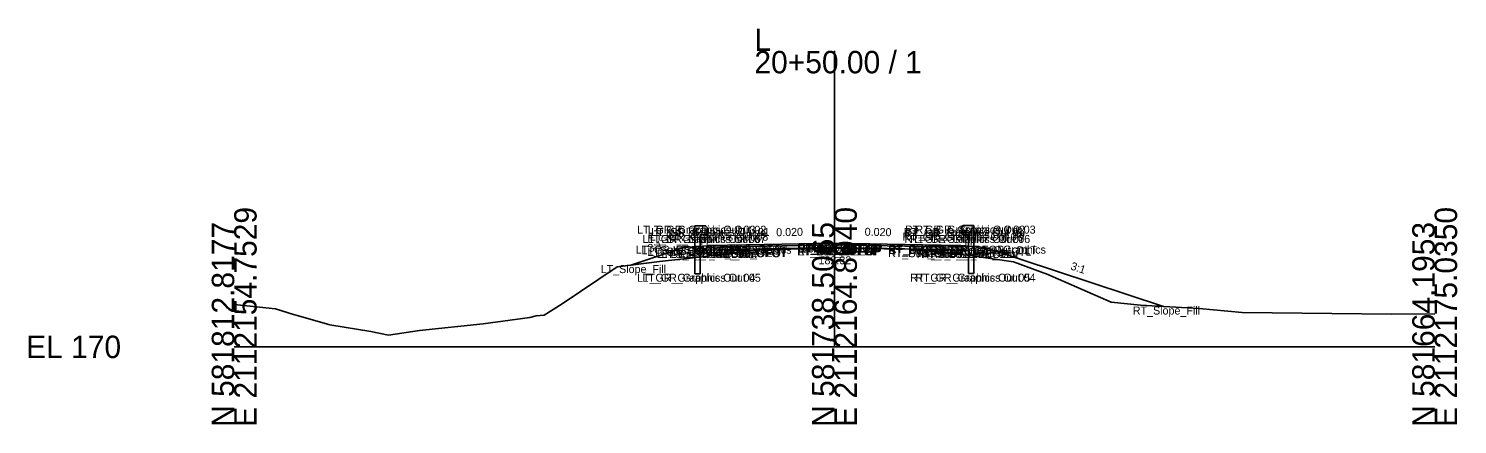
# Model space of a CAD drawing. Extents: x -486 to 1153, y -333 to 9539.
# Drawn here: x 974.3 to 1152.8, y 1490.3 to 1539.8 of the extents above; entities that cross this region are included whole.
import ezdxf

# ---------------------------------------------------------------- set-up
doc = ezdxf.new("R2010")
doc.units = 0
for name, color, linetype in [('Default', 7, 'Continuous'), ('Exist Cross Section Cell', 7, 'Continuous'), ('Exist XS Ground Line', 7, 'Continuous'), ('Prop CMT Guardrail Graphics', 7, 'Continuous'), ('Prop CMT Pvmt Course 1', 7, 'Continuous'), ('Prop CMT Pvmt Course 2', 7, 'Continuous'), ('Prop CMT Pvmt Course 3', 7, 'Continuous'), ('Prop CMT Pvmt Surface', 7, 'Continuous'), ('Prop CMT Pvmt Surface Shoulder', 7, 'Continuous'), ('Prop CMT Shld Paved Course 1', 7, 'Continuous'), ('Prop CMT Shld Paved Course 2', 7, 'Continuous'), ('Prop CMT Shld Paved Course 3', 7, 'Continuous'), ('Prop CMT Slope Grass', 7, 'Continuous'), ('Prop CMT Subgrade Earthwork', 7, 'Continuous'), ('Prop XS Earthwork Shape', 7, 'Continuous'), ('Prop XS SE Text', 7, 'Continuous'), ('Prop XS Side Slope Text', 7, 'Continuous'), ('Scratch_Level_0', 7, 'Continuous')]:
    doc.layers.add(name, color=color, linetype=linetype)

msp = doc.modelspace()

# ---------------------------------------------------------------- linework, layer by layer
at = {"layer": 'Exist Cross Section Cell'}
for p, q in [((1075, 1500), (1075, 1536.98)), ((1000, 1500), (1075, 1500)), ((1075, 1500), (1150, 1500))]:
    msp.add_line(p, q, dxfattribs=at)
at = {"layer": 'Exist XS Ground Line'}
for p, q in [((1067.82, 1512.15), (1074.8, 1512.33)), ((1074.8, 1512.33), (1077.65, 1512.28)), ((1077.65, 1512.28), (1084.77, 1512.2)), ((1084.77, 1512.2), (1088.79, 1511.79)), ((1047.84, 1510), (1053.16, 1510.68)), ((1053.16, 1510.68), (1058.11, 1511.21)), ((1058.11, 1511.21), (1065.16, 1512.09)), ((1065.16, 1512.09), (1067.82, 1512.15)), ((1088.79, 1511.79), (1092.19, 1511.37)), ((1092.19, 1511.37), (1097.38, 1510.62)), ((1097.38, 1510.62), (1101.65, 1509.04)), ((1040.99, 1505.38), (1047.84, 1510)), ((1101.65, 1509.04), (1109.57, 1505.6)), ((1000, 1505.3), (1005.15, 1504.74)), ((1038.72, 1503.97), (1040.99, 1505.38)), ((1109.57, 1505.6), (1113.26, 1505.2)), ((1113.26, 1505.2), (1120.59, 1504.79)), ((1005.15, 1504.74), (1007.42, 1504.05)), ((1007.42, 1504.05), (1008.03, 1503.89)), ((1008.03, 1503.89), (1011.95, 1502.75)), ((1031.11, 1502.88), (1036.95, 1503.68)), ((1036.95, 1503.68), (1037.74, 1503.86)), ((1037.74, 1503.86), (1038.72, 1503.97)), ((1120.59, 1504.79), (1125.96, 1504.3)), ((1125.96, 1504.3), (1144.66, 1504.1)), ((1144.66, 1504.1), (1150, 1504.13)), ((1011.95, 1502.75), (1017.07, 1501.94)), ((1017.07, 1501.94), (1019.29, 1501.47)), ((1019.29, 1501.47), (1023.14, 1502.04)), ((1023.14, 1502.04), (1031.11, 1502.88))]:
    msp.add_line(p, q, dxfattribs=at)
at = {"layer": 'Prop CMT Guardrail Graphics'}
for points in [[(1057.56, 1509.14), (1057.56, 1515.14)], [(1057.56, 1515.14), (1058.89, 1515.14), (1059.16, 1514.85)], [(1059.16, 1514.27), (1058.89, 1513.98), (1058.22, 1513.98)], [(1058.22, 1513.98), (1058.22, 1509.14)], [(1059.16, 1514.85), (1058.89, 1514.56)], [(1058.89, 1514.56), (1059.16, 1514.27)], [(1092.4, 1515.15), (1091.06, 1515.15), (1090.79, 1514.85)], [(1090.79, 1514.85), (1091.06, 1514.56)], [(1091.06, 1514.56), (1090.79, 1514.27)], [(1090.79, 1514.27), (1091.06, 1513.98), (1091.73, 1513.98)], [(1091.73, 1513.98), (1091.73, 1509.15)], [(1092.4, 1509.15), (1092.4, 1515.15)], [(1058.22, 1509.14), (1057.56, 1509.14)], [(1091.73, 1509.15), (1092.4, 1509.15)]]:
    msp.add_lwpolyline(points, dxfattribs=at)
at = {"layer": 'Prop CMT Pvmt Course 1'}
for points in [[(1075, 1512.97), (1064, 1512.75)], [(1064, 1512.54), (1075, 1512.76)], [(1064, 1512.75), (1064, 1512.54)], [(1075, 1512.76), (1075, 1512.97)], [(1075, 1512.97), (1086, 1512.75)], [(1075, 1512.76), (1075, 1512.97)], [(1086, 1512.54), (1075, 1512.76)], [(1086, 1512.75), (1086, 1512.54)]]:
    msp.add_lwpolyline(points, dxfattribs=at)
msp.add_lwpolyline([(1075, 1512.76), (1075, 1512.84), (1075, 1512.84), (1075, 1512.76)], close=True, dxfattribs=at)
msp.add_lwpolyline([(1075, 1512.76), (1075, 1512.84), (1075, 1512.84), (1075, 1512.76)], close=True, dxfattribs=at)
at = {"layer": 'Prop CMT Pvmt Course 2'}
for points in [[(1075, 1512.76), (1064, 1512.54)], [(1064, 1512.54), (1064, 1512.21)], [(1064, 1512.21), (1075, 1512.43)], [(1075, 1512.43), (1075, 1512.76)], [(1075, 1512.43), (1075, 1512.76)], [(1075, 1512.76), (1086, 1512.54)], [(1086, 1512.21), (1075, 1512.43)], [(1086, 1512.54), (1086, 1512.21)]]:
    msp.add_lwpolyline(points, dxfattribs=at)
at = {"layer": 'Prop CMT Pvmt Course 3'}
for points in [[(1075, 1512.43), (1064, 1512.21)], [(1064, 1512.21), (1064, 1512.21)], [(1075, 1512.43), (1075, 1512.43)], [(1075, 1512.43), (1086, 1512.21)], [(1075, 1512.43), (1075, 1512.43)], [(1086, 1512.21), (1086, 1512.21)]]:
    msp.add_lwpolyline(points, dxfattribs=at)
at = {"layer": 'Prop CMT Pvmt Surface'}
for points in [[(1075, 1512.97), (1064, 1512.75)], [(1075, 1512.97), (1086, 1512.75)]]:
    msp.add_lwpolyline(points, dxfattribs=at)
at = {"layer": 'Prop CMT Pvmt Surface Shoulder'}
for points in [[(1064, 1512.75), (1059.26, 1512.65)], [(1086, 1512.75), (1090.69, 1512.65)]]:
    msp.add_lwpolyline(points, dxfattribs=at)
at = {"layer": 'Prop CMT Shld Paved Course 1'}
for points in [[(1064, 1512.75), (1059.26, 1512.65), (1059.05, 1512.44)], [(1059.05, 1512.44), (1064, 1512.54)], [(1064, 1512.54), (1064, 1512.75)], [(1086, 1512.75), (1090.69, 1512.65), (1090.9, 1512.44)], [(1086, 1512.54), (1086, 1512.75)], [(1090.9, 1512.44), (1086, 1512.54)]]:
    msp.add_lwpolyline(points, dxfattribs=at)
at = {"layer": 'Prop CMT Shld Paved Course 2'}
for points in [[(1064, 1512.54), (1059.05, 1512.44), (1058.71, 1512.1)], [(1058.71, 1512.1), (1064, 1512.21)], [(1064, 1512.21), (1064, 1512.54)], [(1086, 1512.54), (1090.9, 1512.44), (1091.24, 1512.1)], [(1086, 1512.21), (1086, 1512.54)], [(1091.24, 1512.1), (1086, 1512.21)]]:
    msp.add_lwpolyline(points, dxfattribs=at)
at = {"layer": 'Prop CMT Shld Paved Course 3'}
for points in [[(1064, 1512.21), (1058.71, 1512.1)], [(1064, 1512.21), (1064, 1512.21)], [(1086, 1512.21), (1091.24, 1512.1)], [(1086, 1512.21), (1086, 1512.21)], [(1058.71, 1512.1), (1058.71, 1512.1), (1058.71, 1512.1)], [(1091.24, 1512.1), (1091.24, 1512.1), (1091.24, 1512.1)]]:
    msp.add_lwpolyline(points, dxfattribs=at)
at = {"layer": 'Prop CMT Slope Grass'}
for points in [[(1056.16, 1512.4), (1049.55, 1510.22)], [(1059.16, 1512.64), (1056.16, 1512.4)], [(1059.26, 1512.65), (1059.16, 1512.64)], [(1090.69, 1512.65), (1090.79, 1512.65)], [(1090.79, 1512.65), (1093.79, 1512.41)], [(1093.79, 1512.41), (1116.1, 1505.04)]]:
    msp.add_lwpolyline(points, dxfattribs=at)
at = {"layer": 'Prop CMT Subgrade Earthwork'}
for points in [[(1058.71, 1512.1), (1058.24, 1512.57)], [(1064, 1512.21), (1058.71, 1512.1)], [(1075, 1512.43), (1064, 1512.21)], [(1075, 1512.43), (1086, 1512.21)], [(1086, 1512.21), (1091.24, 1512.1)], [(1091.24, 1512.1), (1091.72, 1512.57)]]:
    msp.add_lwpolyline(points, dxfattribs=at)
at = {"layer": 'Prop XS Earthwork Shape'}
msp.add_lwpolyline([(1075, 1512.43), (1086, 1512.21), (1091.24, 1512.1), (1091.72, 1512.57), (1093.79, 1512.41), (1116.1, 1505.04), (1113.26, 1505.2), (1109.57, 1505.6), (1101.65, 1509.04), (1097.38, 1510.62), (1092.19, 1511.37), (1088.79, 1511.79), (1084.77, 1512.2), (1077.65, 1512.28), (1074.8, 1512.33), (1067.82, 1512.15), (1065.16, 1512.09), (1058.11, 1511.21), (1053.16, 1510.68), (1049.55, 1510.22), (1056.16, 1512.4), (1058.24, 1512.57), (1058.71, 1512.1), (1064, 1512.21)], close=True, dxfattribs=at)

# ---------------------------------------------------------------- texts
at = {"layer": 'Default'}
for s, height, p in [('182.32', 1, (1073.01, 1510.32)), ('-', 0.0001, (1000, 1500))]:
    msp.add_text(s, height=height, dxfattribs=at).set_placement(p)
at = {"layer": 'Exist Cross Section Cell'}
for s, p in [('L', (1065, 1536.98)), ('20+50.00 / 1', (1065, 1534.18)), ('EL 170', (974, 1498.6))]:
    msp.add_text(s, height=2.8, dxfattribs=at).set_placement(p)
for s, p in [('E 2112154.7529', (1002.8, 1490)), ('E 2112164.8940', (1077.8, 1490)), ('E 2112175.0350', (1152.8, 1490)), ('N 581812.8177', (1000, 1490)), ('N 581738.5065', (1075, 1490)), ('N 581664.1953', (1150, 1490))]:
    msp.add_text(s, height=2.8, rotation=90, dxfattribs=at).set_placement(p)
at = {"layer": 'Prop XS SE Text'}
for rotation, p in [(1.1458, (1067.73, 1513.82)), (358.8542, (1078.77, 1513.89))]:
    msp.add_text('0.020', height=1, rotation=rotation, dxfattribs=at).set_placement(p)
at = {"layer": 'Prop XS Side Slope Text'}
for rotation, p in [(18.2629, (1051.87, 1511.78)), (341.7371, (1104.43, 1509.69))]:
    msp.add_text('3:1', height=1, rotation=rotation, dxfattribs=at).set_placement(p)
at = {"layer": 'Scratch_Level_0'}
for s, p in [('LT_GR_Graphics Out 03', (1050.34, 1514.14)), ('LT_GR_Graphics Out 06', (1051, 1512.98)), ('LT_GR_Graphics Out 07', (1051.65, 1512.98)), ('LT_GR_Graphics Out 09', (1051.67, 1513.56)), ('LT_GR_Graphics Out 02', (1051.69, 1514.14)), ('LT_GR_Graphics Out 08', (1051.93, 1513.27)), ('LT_GR_Graphics Out 01', (1052.11, 1513.85)), ('RT_GR_Graphics Out 08', (1083.5, 1513.27)), ('RT_GR_Graphics Out 01', (1083.68, 1513.85)), ('RT_GR_Graphics Out 07', (1083.76, 1512.98)), ('RT_GR_Graphics Out 09', (1083.78, 1513.56)), ('RT_GR_Graphics Out 02', (1083.81, 1514.15)), ('RT_GR_Graphics Out 06', (1084.44, 1512.98)), ('RT_GR_Graphics Out 03', (1085.12, 1514.15)), ('LT_GS_OS_GR_Face_Graphics', (1050.16, 1511.64)), ('LT_Sub_Trench_Out_DLT', (1050.89, 1511.57)), ('LT_GS_OS_CTL', (1051.63, 1511.4)), ('LT_PS2_OEOP', (1054.84, 1511.44)), ('LT_PS1_OEOP', (1055.17, 1511.65)), ('LT_PV2_OEOT', (1059.75, 1511.54)), ('LT_PV3_OEOT', (1059.75, 1511.21)), ('LT_Sub_OEOT', (1059.77, 1511.21)), ('LT_PV1_OEOT', (1059.87, 1511.75)), ('RT_PV2_OEEOP', (1070.33, 1511.76)), ('RT_PV3_OEEOP', (1070.33, 1511.43)), ('RT_Sub_OEEOP', (1070.36, 1511.43)), ('LT_PV2_OEEOP', (1070.39, 1511.76)), ('LT_PV3_OEEOP', (1070.39, 1511.43)), ('LT_Sub_OEEOP', (1070.42, 1511.43)), ('RT_PV1_OEEOP', (1070.45, 1511.84)), ('LT_PV1_OEEOP', (1070.51, 1511.84)), ('RT_PV2_IEEOP', (1070.71, 1511.76)), ('LT_PV2_IEEOP', (1070.77, 1511.76)), ('RT_PV1_IEEOP', (1070.83, 1511.84)), ('LT_PV1_IEEOP', (1070.89, 1511.84)), ('PV2_PGL', (1072.35, 1511.76)), ('PV1_PGL', (1072.47, 1511.97)), ('RT_PV2_OEOT', (1081.69, 1511.54)), ('RT_PV3_OEOT', (1081.69, 1511.21)), ('RT_Sub_OEOT', (1081.71, 1511.21)), ('RT_GS_OS_GR_Face_Graphics', (1081.73, 1511.65)), ('RT_PV1_OEOT', (1081.81, 1511.75)), ('RT_Sub_Trench_Out_DLT', (1084.31, 1511.57)), ('RT_PS1_OEOP', (1086.54, 1511.65)), ('RT_PS2_OEOP', (1086.63, 1511.44)), ('RT_GS_OS_CTL', (1089.2, 1511.41)), ('LT_Sub_Trench_Out', (1052.82, 1511.1)), ('LT_PS3_Shelf_Out', (1053.37, 1511.1)), ('LT_PS3_OEOP', (1054.5, 1511.1)), ('RT_Sub_Trench_Out', (1085.29, 1511.1)), ('RT_PS3_Shelf_Out', (1085.84, 1511.1)), ('RT_PS3_OEOP', (1086.97, 1511.1)), ('LT_Slope_Fill', (1045.79, 1509.22)), ('LT_GR_Graphics Out 04', (1050.33, 1508.14)), ('LT_GR_Graphics Out 05', (1051, 1508.14)), ('RT_GR_Graphics Out 05', (1084.45, 1508.15)), ('RT_GR_Graphics Out 04', (1085.11, 1508.15)), ('RT_Slope_Fill', (1112.28, 1504.04))]:
    msp.add_text(s, height=1, dxfattribs=at).set_placement(p)

doc.saveas('drawing.dxf')
